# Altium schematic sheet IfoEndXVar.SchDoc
size A; DocumentNumber: 3; SheetNumber: 3; SheetTotal: 8; pInstance: Corner
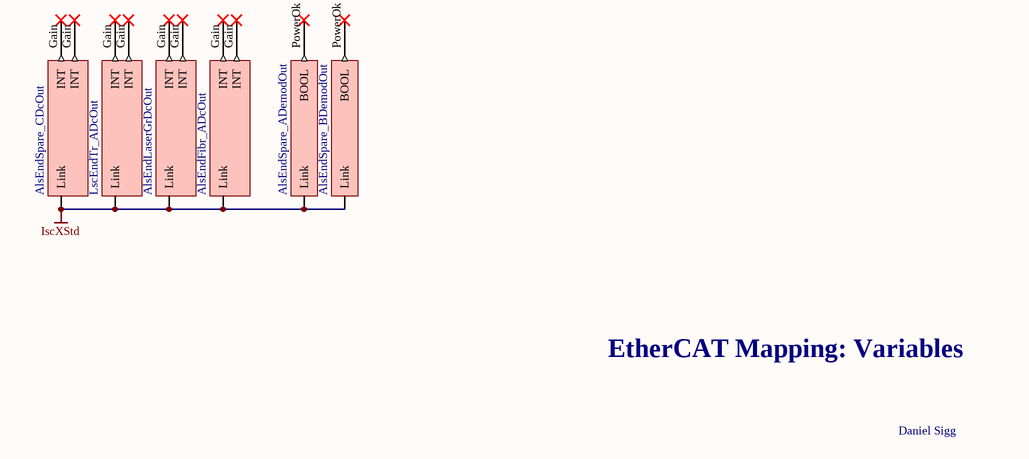
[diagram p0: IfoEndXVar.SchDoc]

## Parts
V48  AlsEndSpare_CDcOut  (no BOM)
V53  LscEndTr_ADcOut  (no BOM)
V55  AlsEndLaserGrDcOut  (no BOM)
V57  AlsEndFibr_ADcOut  (no BOM)
V59  AlsEndSpare_ADemodOut  (no BOM)
V61  AlsEndSpare_BDemodOut  (no BOM)

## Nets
IscXStd: V48.0(Link) V53.0(Link) V55.0(Link) V57.0(Link) V59.?1(Link) V61.?1(Link)

Not connected (* = marked no-connect by the designer): V48 Gain(INT)*; V53 Gain(INT)*; V55 Gain(INT)*; V57 Gain(INT)*; V59 PowerOk(BOOL)*; V61 PowerOk(BOOL)*

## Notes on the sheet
- EtherCAT Mapping: Variables
- Daniel Sigg

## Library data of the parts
V48 V53 V55 V57 = DCPower_DCPowerOutStruct: DCPowerOutStruct; BoxType: Variable; Instance: H1IscEndX Instance; PLC: H1IscEndX; Task: IscEStd
V59 V61 = Demodulator_DemodulatorOutStruct: DemodulatorOutStruct; BoxType: Variable; Instance: H1IscEndX Instance; PLC: H1IscEndX; Task: IscEStd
